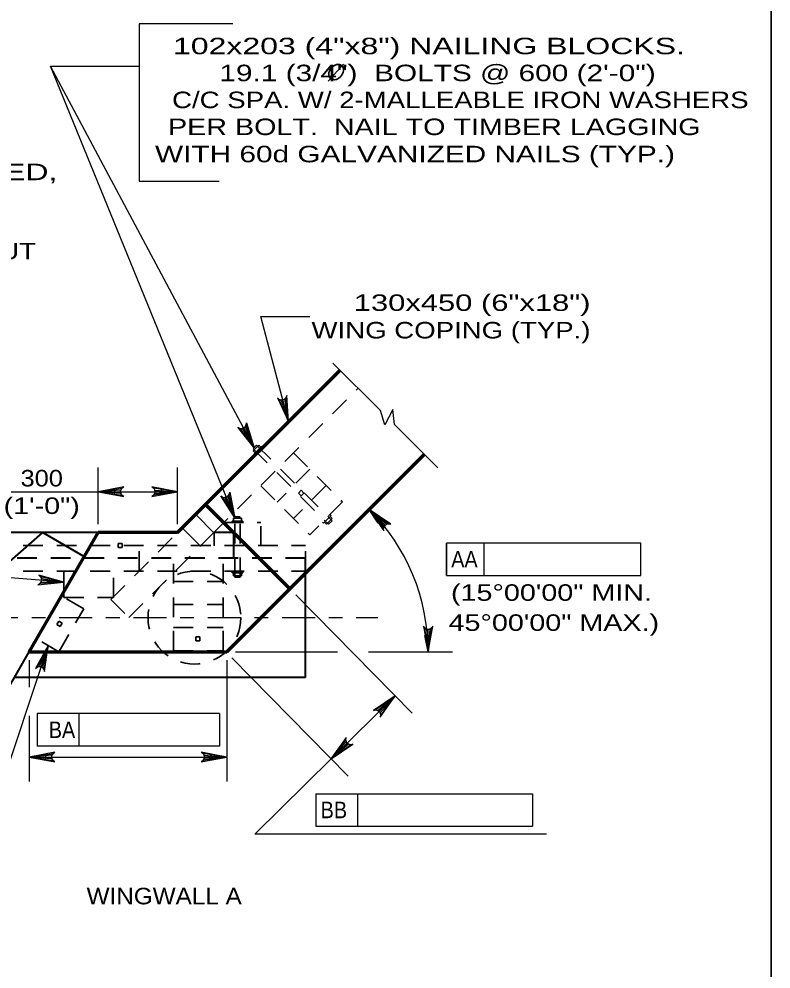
# Model space of a CAD drawing. Extents: x -6.4 to 73.1, y -66 to 0.
# Drawn here: x 27.78 to 33.25, y -57.61 to -50.7 of the extents above; entities that cross this region are included whole.
import ezdxf
from ezdxf.enums import TextEntityAlignment as Align

# ---------------------------------------------------------------- set-up
doc = ezdxf.new("R2010")
doc.units = 0
doc.header["$LTSCALE"] = 0.048
doc.linetypes.add('DOT_DASHED', pattern=[7.7, 5, -1.2, 0.3, -1.2])
doc.linetypes.add('MEDIUM_DASHED', pattern=[4.5, 3, -1.5])
for name, color, linetype, lineweight in [('1', 7, 'Continuous', 13), ('4', 7, 'Continuous', 25), ('5', 7, 'Continuous', 25), ('52', 7, 'Continuous', 25)]:
    doc.layers.add(name, color=color, linetype=linetype, lineweight=lineweight)

msp = doc.modelspace()

# ---------------------------------------------------------------- hatches: boundary and pattern name
at = {"layer": '4'}
msp.add_hatch(color=256, dxfattribs=at).paths.add_polyline_path([(28.10958, -54.793), (27.99108, -54.79333), (27.99267, -54.77375)])
at = {"layer": '5'}
for points in [[(29.7435, -53.62658), (29.70383, -53.51483), (29.72283, -53.50983)], [(28.47667, -54.11725), (28.47667, -54.15667), (28.35858, -54.13692)], [(28.818, -54.11725), (28.818, -54.15667), (28.93608, -54.13692)], [(30.42392, -54.33908), (30.39492, -54.36575), (30.32933, -54.26558)], [(30.73342, -55.18283), (30.77275, -55.18125), (30.75783, -55.30008)], [(27.99592, -55.25533), (27.96775, -55.3705), (27.94908, -55.36425)], [(30.42025, -55.68892), (30.44792, -55.717), (30.51825, -55.62008)], [(30.12342, -55.98108), (30.151, -56.00908), (30.05308, -56.07792)], [(27.97658, -56.04525), (27.97658, -56.08458), (27.8585, -56.06492)], [(29.17675, -56.04525), (29.17675, -56.08458), (29.29483, -56.06492)]]:
    msp.add_hatch(color=256, dxfattribs=at).paths.add_polyline_path(points)

# ---------------------------------------------------------------- linework, layer by layer
at = {"layer": '1', "lineweight": 35}
msp.add_lwpolyline([(1.75, -65.25), (33.25, -65.25), (33.25, -44.75), (1.75, -44.75)], close=True, dxfattribs=at)
at = {"layer": '4'}
for p, q in [((29.49358, -53.81683), (28.0125, -51.04483)), ((30.06583, -53.2015), (30.41025, -53.54583)), ((30.51275, -53.64833), (30.49975, -53.539)), ((30.51275, -53.64833), (30.82783, -53.9635))]:
    msp.add_line(p, q, dxfattribs=at)
at = {"layer": '4', "lineweight": 70}
for p, q in [((28.93608, -54.43392), (30.11717, -53.25283)), ((29.29483, -55.30008), (30.72967, -53.86525)), ((29.14025, -54.22975), (29.75267, -54.84225)), ((27.8585, -55.30008), (28.35858, -54.43392)), ((28.93608, -54.43392), (28.35858, -54.43392)), ((27.8585, -55.30008), (29.29483, -55.30008))]:
    msp.add_line(p, q, dxfattribs=at)
at = {"layer": '4', "linetype": 'MEDIUM_DASHED', "lineweight": 35}
for p, q in [((29.19917, -54.43392), (30.24875, -53.38433)), ((29.485, -53.82542), (30.03317, -54.37358)), ((29.51108, -53.79925), (30.05925, -54.3475)), ((29.77867, -53.85442), (30.13567, -54.21142)), ((29.89792, -53.97367), (29.65942, -54.21225)), ((29.54017, -54.09292), (29.89717, -54.44992)), ((30.01683, -54.09258), (29.77825, -54.33108)), ((30.13567, -54.21142), (29.89717, -54.44992)), ((29.35325, -54.75817), (29.35325, -54.31917)), ((29.39008, -54.75817), (29.39008, -54.31917)), ((30.05183, -54.31017), (29.99592, -54.36608)), ((30.05183, -54.31017), (30.04433, -54.30275)), ((29.27175, -54.36133), (29.54033, -54.36133)), ((29.54033, -54.53), (29.54033, -54.36133)), ((29.99592, -54.36608), (29.9885, -54.35867)), ((30.01825, -54.37358), (30.00333, -54.35867)), ((28.45, -54.92), (28.93608, -54.43392)), ((28.5815, -55.05158), (29.19917, -54.43392)), ((26.59325, -54.52792), (29.86575, -54.52792)), ((28.65608, -54.714), (28.65608, -54.52792)), ((29.86575, -54.714), (29.86575, -54.52792)), ((28.90642, -55.29242), (28.90642, -54.61992)), ((29.26733, -55.29242), (29.26733, -54.61992)), ((26.59325, -54.714), (29.86575, -54.714)), ((28.4705, -54.90642), (28.4705, -54.714)), ((29.33217, -54.7265), (29.33217, -54.716)), ((29.33217, -54.7265), (29.41117, -54.7265)), ((29.34267, -54.74758), (29.34267, -54.7265)), ((29.40067, -54.74758), (29.40067, -54.7265)), ((29.41117, -54.7265), (29.41117, -54.716)), ((28.90642, -54.78808), (29.26733, -54.78808)), ((29.34267, -54.74758), (29.40067, -54.74758)), ((29.35325, -54.75817), (29.39008, -54.75817)), ((28.25375, -54.9875), (28.09267, -54.8945)), ((28.10958, -54.90642), (28.4705, -54.90642)), ((28.45, -54.92), (28.5815, -55.05158)), ((28.07325, -55.30008), (28.25375, -54.9875)), ((28.90642, -54.95617), (29.26733, -54.95617)), ((28.90642, -55.12425), (29.26733, -55.12425)), ((28.07325, -55.30008), (27.91217, -55.20708)), ((28.90642, -55.29242), (29.26733, -55.29242))]:
    msp.add_line(p, q, dxfattribs=at)
at = {"layer": '4', "lineweight": 35}
for p, q in [((29.51108, -53.79925), (29.485, -53.82542)), ((29.526, -53.79925), (29.485, -53.84025)), ((29.485, -53.84025), (29.49992, -53.85517)), ((29.54833, -53.80675), (29.4925, -53.86267)), ((29.526, -53.79925), (29.54092, -53.81417)), ((29.54833, -53.80675), (29.55583, -53.81417)), ((29.4925, -53.86267), (29.49992, -53.87008)), ((29.06767, -54.30242), (29.20083, -54.43558)), ((29.34267, -54.32967), (29.40067, -54.32967)), ((29.34267, -54.32967), (29.34267, -54.35075)), ((29.35325, -54.31917), (29.39008, -54.31917)), ((29.40067, -54.32967), (29.40067, -54.35075)), ((30.05925, -54.33258), (30.04433, -54.31767)), ((29.33217, -54.35075), (29.41117, -54.35075)), ((29.33217, -54.35075), (29.33217, -54.36133)), ((29.41117, -54.35075), (29.41117, -54.36133)), ((30.05925, -54.33258), (30.01825, -54.37358)), ((30.05925, -54.3475), (30.03317, -54.37358)), ((28.96983, -54.40025), (29.103, -54.53342)), ((29.203, -54.53), (29.203, -54.43008)), ((28.10958, -54.90642), (28.10958, -54.714))]:
    msp.add_line(p, q, dxfattribs=at)
at = {"layer": '4', "lineweight": 40}
for p, q in [((28.35858, -54.43392), (26.59325, -54.43392)), ((27.03808, -55.23275), (27.957, -54.43392)), ((27.957, -54.43392), (28.25817, -54.60783)), ((29.34442, -54.43392), (29.19917, -54.43392)), ((29.34442, -54.61992), (29.34442, -54.43392)), ((29.86575, -55.48658), (29.86575, -54.61992)), ((27.55142, -55.83192), (27.8585, -55.30008)), ((29.86575, -55.48608), (27.75108, -55.48608))]:
    msp.add_line(p, q, dxfattribs=at)
at = {"layer": '4', "linetype": 'MEDIUM_DASHED', "lineweight": 40}
msp.add_line((29.86575, -54.61992), (26.59325, -54.61992), dxfattribs=at)
at = {"layer": '4', "linetype": 'DOT_DASHED'}
msp.add_line((21.5955, -55.05158), (30.39275, -55.05158), dxfattribs=at)
at = {"layer": '4'}
for points in [[(30.49975, -53.539), (30.4435, -53.65142), (30.41025, -53.54583)], [(28.1095, -54.793), (26.4685, -54.6605), (26.42267, -54.6605)]]:
    msp.add_lwpolyline(points, dxfattribs=at)
at = {"layer": '4', "linetype": 'MEDIUM_DASHED', "lineweight": 35}
for points in [[(29.83492, -54.16617), (29.85467, -54.1465), (29.83492, -54.12675), (29.81517, -54.1465)], [(28.50475, -54.54225), (28.53267, -54.54225), (28.53267, -54.51433), (28.50475, -54.51433)], [(28.08333, -55.11617), (28.09725, -55.092), (28.07308, -55.078), (28.05917, -55.10217)], [(29.069, -55.22033), (29.09692, -55.22033), (29.09692, -55.19242), (29.069, -55.19242)]]:
    msp.add_lwpolyline(points, close=True, dxfattribs=at)
at = {"layer": '4'}
msp.add_lwpolyline([(28.10958, -54.793), (27.99108, -54.79333), (27.99267, -54.77375)], close=True, dxfattribs=at)
at = {"layer": '4', "linetype": 'MEDIUM_DASHED', "lineweight": 35}
msp.add_circle((29.0589, -55.05157), 0.3376, dxfattribs=at)
at = {"layer": '5'}
for p, q in [((29.33883, -50.73742), (28.65608, -50.73742)), ((28.35858, -54.37242), (28.35858, -53.95975)), ((28.93608, -54.37242), (28.93608, -53.95975)), ((27.58925, -54.13692), (28.93608, -54.13692)), ((32.30408, -54.51008), (30.89208, -54.51008)), ((30.89208, -54.51008), (30.89208, -54.74633)), ((30.89208, -54.74633), (30.89208, -54.51008)), ((31.16592, -54.74633), (31.16592, -54.51008)), ((32.30408, -54.74633), (32.30408, -54.51008)), ((30.89208, -54.74633), (32.30408, -54.74633)), ((29.79583, -54.88608), (30.6425, -55.74642)), ((27.99592, -55.25533), (27.303, -57.32725)), ((27.85842, -55.36158), (27.85842, -55.55792)), ((29.29483, -55.36158), (29.29483, -56.24208)), ((29.33067, -55.34392), (30.17733, -56.20417)), ((29.35633, -55.30008), (30.09975, -55.30008)), ((30.32333, -55.30008), (30.93492, -55.30008)), ((27.85842, -55.76483), (27.85842, -56.24208)), ((29.2405, -55.74867), (27.91592, -55.74867)), ((27.91592, -55.74867), (27.91592, -55.98492)), ((28.21833, -55.74867), (28.21833, -55.98492)), ((29.2405, -55.74867), (29.2405, -55.98492)), ((29.2405, -55.98492), (27.91592, -55.98492)), ((27.8585, -56.06492), (29.29483, -56.06492)), ((29.942, -56.33133), (31.51683, -56.33133)), ((29.942, -56.33133), (29.94208, -56.5675)), ((30.2445, -56.33133), (30.24442, -56.56758)), ((31.51683, -56.33133), (31.51683, -56.5675)), ((29.94208, -56.5675), (31.51683, -56.5675)), ((29.49892, -56.62325), (31.61808, -56.62325))]:
    msp.add_line(p, q, dxfattribs=at)
at = {"layer": '5', "lineweight": 35}
msp.add_line((30.03142, -51.15317), (30.14342, -51.03058), dxfattribs=at)
at = {"layer": '5'}
for points in [[(28.65608, -50.73742), (28.65608, -51.88075), (29.23933, -51.88075)], [(29.35325, -54.326), (28.0125, -51.04483), (28.65608, -51.04483)], [(29.7435, -53.62658), (29.54192, -52.863), (29.8965, -52.863)], [(29.7435, -53.62658), (29.72975, -53.43742), (29.72375, -53.45383), (29.71358, -53.46417), (29.702, -53.4695), (29.68942, -53.47058), (29.67542, -53.46658), (29.66208, -53.45525), (29.7435, -53.62658), (29.67542, -53.46658), (29.68942, -53.47058), (29.7435, -53.62658), (29.702, -53.4695), (29.71358, -53.46417), (29.7435, -53.62658), (29.72375, -53.45383)], [(28.35858, -54.13692), (28.545, -54.17183), (28.53067, -54.16192), (28.52325, -54.14942), (28.52108, -54.13692), (28.52325, -54.12442), (28.53067, -54.11192), (28.545, -54.102), (28.35858, -54.13692), (28.53067, -54.11192), (28.52325, -54.12442), (28.35858, -54.13692), (28.52108, -54.13692), (28.52325, -54.14942), (28.35858, -54.13692), (28.53067, -54.16192)], [(28.93608, -54.13692), (28.74967, -54.102), (28.764, -54.11192), (28.77142, -54.12442), (28.77358, -54.13692), (28.77142, -54.14942), (28.764, -54.16192), (28.74967, -54.17183), (28.93608, -54.13692), (28.764, -54.16192), (28.77142, -54.14942), (28.93608, -54.13692), (28.77358, -54.13692), (28.77142, -54.12442), (28.93608, -54.13692), (28.764, -54.11192)], [(30.32933, -54.26558), (30.43642, -54.42208), (30.43333, -54.40492), (30.43692, -54.39083), (30.44425, -54.3805), (30.45458, -54.37317), (30.46867, -54.36958), (30.48583, -54.37267), (30.32933, -54.26558), (30.46867, -54.36958), (30.45458, -54.37317), (30.32933, -54.26558), (30.44425, -54.3805), (30.43692, -54.39083), (30.32933, -54.26558), (30.43333, -54.40492)], [(28.10958, -54.793), (27.92658, -54.74317), (27.94008, -54.75425), (27.9465, -54.76725), (27.94758, -54.77992), (27.9445, -54.79225), (27.93608, -54.80408), (27.921, -54.81283), (28.10958, -54.793), (27.93608, -54.80408), (27.9445, -54.79225), (28.10958, -54.793), (27.94758, -54.77992), (27.9465, -54.76725), (28.10958, -54.793), (27.94008, -54.75425)], [(30.75783, -55.30008), (30.79275, -55.11367), (30.78283, -55.128), (30.77033, -55.13542), (30.75783, -55.13758), (30.74533, -55.13542), (30.73283, -55.128), (30.72292, -55.11367), (30.75783, -55.30008), (30.73283, -55.128), (30.74533, -55.13542), (30.75783, -55.30008), (30.75783, -55.13758), (30.77033, -55.13542), (30.75783, -55.30008), (30.78283, -55.128)], [(27.99592, -55.25533), (27.90367, -55.421), (27.91767, -55.41058), (27.93183, -55.4075), (27.94442, -55.40942), (27.95558, -55.41542), (27.96508, -55.42642), (27.96992, -55.44325), (27.99592, -55.25533), (27.96508, -55.42642), (27.95558, -55.41542), (27.99592, -55.25533), (27.94442, -55.40942), (27.93183, -55.4075), (27.99592, -55.25533), (27.91767, -55.41058)], [(30.51817, -55.62008), (30.05308, -56.07792), (29.499, -56.62325)], [(30.51817, -55.62008), (30.36083, -55.72592), (30.378, -55.723), (30.39208, -55.72667), (30.40233, -55.73408), (30.40958, -55.7445), (30.41308, -55.75858), (30.40983, -55.77575), (30.51817, -55.62008), (30.41308, -55.75858), (30.40958, -55.7445), (30.51817, -55.62008), (30.40233, -55.73408), (30.39208, -55.72667), (30.51817, -55.62008), (30.378, -55.723)], [(30.05308, -56.07792), (30.21042, -55.97208), (30.19325, -55.975), (30.17917, -55.97133), (30.16892, -55.96392), (30.16167, -55.9535), (30.15817, -55.93942), (30.16142, -55.92225), (30.05308, -56.07792), (30.15817, -55.93942), (30.16167, -55.9535), (30.05308, -56.07792), (30.16892, -55.96392), (30.17917, -55.97133), (30.05308, -56.07792), (30.19325, -55.975)], [(27.8585, -56.06492), (28.04492, -56.09983), (28.03058, -56.08992), (28.02317, -56.07742), (28.021, -56.06492), (28.02317, -56.05242), (28.03058, -56.03992), (28.04492, -56.03), (27.8585, -56.06492), (28.03058, -56.03992), (28.02317, -56.05242), (27.8585, -56.06492), (28.021, -56.06492), (28.02317, -56.07742), (27.8585, -56.06492), (28.03058, -56.08992)], [(29.29483, -56.06492), (29.10842, -56.03), (29.12275, -56.03992), (29.13017, -56.05242), (29.13233, -56.06492), (29.13017, -56.07742), (29.12275, -56.08992), (29.10842, -56.09983), (29.29483, -56.06492), (29.12275, -56.08992), (29.13017, -56.07742), (29.29483, -56.06492), (29.13233, -56.06492), (29.13017, -56.05242), (29.29483, -56.06492), (29.12275, -56.03992)]]:
    msp.add_lwpolyline(points, dxfattribs=at)
for points in [[(29.7435, -53.62658), (29.70383, -53.51483), (29.72283, -53.50983)], [(28.47667, -54.11725), (28.47667, -54.15667), (28.35858, -54.13692)], [(28.818, -54.11725), (28.818, -54.15667), (28.93608, -54.13692)], [(30.42392, -54.33908), (30.39492, -54.36575), (30.32933, -54.26558)], [(30.73342, -55.18283), (30.77275, -55.18125), (30.75783, -55.30008)], [(27.99592, -55.25533), (27.96775, -55.3705), (27.94908, -55.36425)], [(30.42025, -55.68892), (30.44792, -55.717), (30.51825, -55.62008)], [(30.12342, -55.98108), (30.151, -56.00908), (30.05308, -56.07792)], [(27.97658, -56.04525), (27.97658, -56.08458), (27.8585, -56.06492)], [(29.17675, -56.04525), (29.17675, -56.08458), (29.29483, -56.06492)]]:
    msp.add_lwpolyline(points, close=True, dxfattribs=at)
msp.add_arc((29.2948, -55.30007), 1.46295, 359.99886, 45.00036, dxfattribs=at)
at = {"layer": '5', "lineweight": 35}
msp.add_spline([(30.13175, -51.04267), (30.123, -51.03583), (30.11425, -51.03342), (30.10325, -51.03242), (30.097, -51.03242), (30.08625, -51.03492), (30.07642, -51.03942), (30.0695, -51.04333), (30.05625, -51.05392), (30.04592, -51.06742), (30.03967, -51.08008), (30.036, -51.09167), (30.03492, -51.10242), (30.036, -51.11167), (30.0405, -51.12483), (30.04525, -51.13167), (30.05492, -51.13892), (30.06942, -51.14242), (30.08592, -51.14192), (30.10675, -51.13242), (30.122, -51.11933), (30.1335, -51.10342), (30.141, -51.08683), (30.1435, -51.06842), (30.14025, -51.05658), (30.13225, -51.04267)], degree=3, dxfattribs=at)
at = {"layer": '52'}
for points in [[(29.49358, -53.81683), (29.37492, -53.66892), (29.39042, -53.67683), (29.405, -53.6775), (29.417, -53.6735), (29.427, -53.66575), (29.43458, -53.65333), (29.43658, -53.63592), (29.49358, -53.81683), (29.43458, -53.65333), (29.427, -53.66575), (29.49358, -53.81683), (29.417, -53.6735), (29.405, -53.6775), (29.49358, -53.81683), (29.39042, -53.67683)], [(29.35325, -54.326), (29.25042, -54.16667), (29.265, -54.17617), (29.27942, -54.17833), (29.29175, -54.17558), (29.3025, -54.16883), (29.31133, -54.15725), (29.31508, -54.14017), (29.35325, -54.326), (29.31133, -54.15725), (29.3025, -54.16883), (29.35325, -54.326), (29.29175, -54.17558), (29.27942, -54.17833), (29.35325, -54.326), (29.265, -54.17617)]]:
    msp.add_lwpolyline(points, dxfattribs=at)

# ---------------------------------------------------------------- texts
at = {"layer": '5'}
for s, width, p in [('102x203 (4"x8") NAILING BLOCKS.  ', 1.45, (32.75358, -50.95792)), ('19.1 (3/4")  BOLTS @ 600 (2\'-0")', 1.35, (32.41233, -51.15367)), ('C/C SPA. W/ 2-MALLEABLE IRON WASHERS', 1.25, (33.08708, -51.3495)), ('PER BOLT.  NAIL TO TIMBER LAGGING', 1.3, (32.73808, -51.54525)), ('WITH 60d GALVANIZED NAILS (TYP.)', 1.35, (32.55192, -51.74292)), ('130x450 (6"x18")', 1.4, (31.93783, -52.82308)), ('WING COPING (TYP.)', 1.25, (31.93783, -53.02308))]:
    msp.add_text(s, height=0.12, dxfattribs=dict(at, width=width)).set_placement(p, align=Align.RIGHT)
for s, width, p in [('4-102x203 (4"x8"), NAIL LAMINATED,', 1.45, (24.09558, -51.873)), ('NAIL ABUTMENT BACKWALL TO STRUT ', 1.25, (24.09558, -52.44883)), ('WINGWALL A', 1.1, (28.27492, -57.13525))]:
    msp.add_text(s, height=0.12, dxfattribs=dict(at, width=width)).set_placement(p)
for s, width, p in [('300', 1.15, (27.94854, -54.09858)), ('(1\'-0")', 1.3, (27.94854, -54.29858)), ('AA', 0.9, (31.02163, -54.68692)), ('(15°00\'00" MIN.', 1.3, (31.65421, -54.92967)), ('45°00\'00" MAX.)', 1.3, (31.67121, -55.148))]:
    msp.add_text(s, height=0.12, dxfattribs=dict(at, width=width)).set_placement(p, align=Align.CENTER)
at = {"layer": '5', "width": 0.9}
for s, rotation, p in [('BA', 0.062, (28.09594, -55.92681)), ('BB', 359.936, (30.07235, -56.50928))]:
    msp.add_text(s, height=0.12, rotation=rotation, dxfattribs=at).set_placement(p, align=Align.CENTER)

doc.saveas('drawing.dxf')
